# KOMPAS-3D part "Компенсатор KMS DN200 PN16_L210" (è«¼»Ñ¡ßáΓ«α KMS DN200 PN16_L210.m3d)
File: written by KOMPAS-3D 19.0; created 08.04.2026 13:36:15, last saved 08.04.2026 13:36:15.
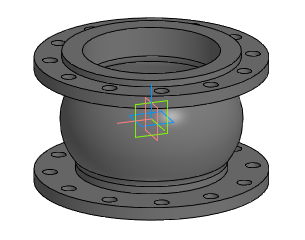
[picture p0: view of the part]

Document properties: Автор: Энергия; Полное имя файла: Z:\3.Личные\kachalov\3d для проектировщиков\7.1 Компенсатор\stp_Компенсатор KSM\Компенсатор KMS DN200 PN16_L210.m3d

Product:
- Part/product: Компенсатор KMS DN200 PN16_L210

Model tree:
1. Операция без истории:1  (labels: Компенсатор KMS DN200 PN16_L210)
